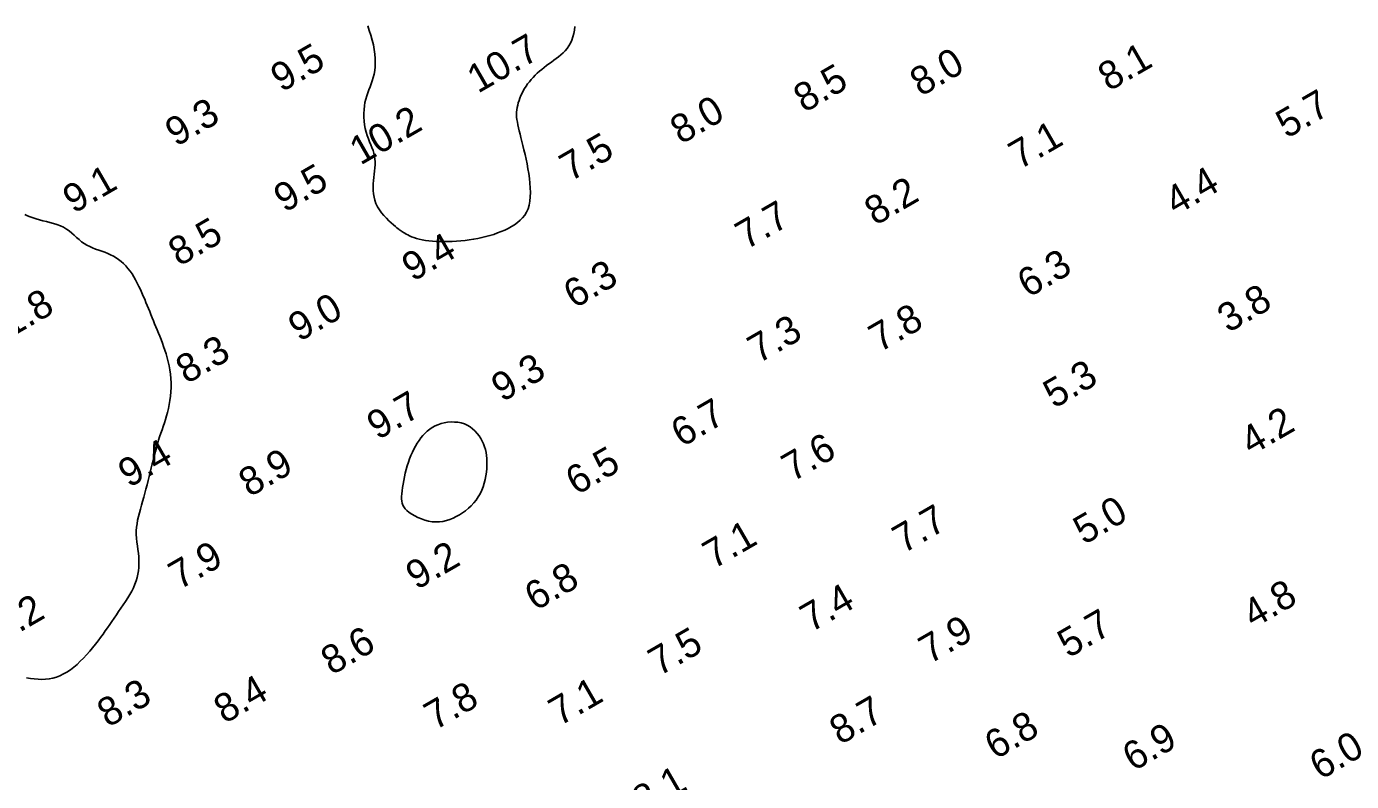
# Model space of a CAD drawing. Extents: x 3024098 to 3056816, y 418252 to 509144.
# Drawn here: x 3033611.9 to 3033845.6, y 418564.6 to 418697.7 of the extents above; entities that cross this region are included whole.
import ezdxf

# ---------------------------------------------------------------- set-up
doc = ezdxf.new("R2010")
doc.units = 0
doc.layers.add('V-CHAN-CONT-EL10', color=7, linetype='Continuous')
doc.layers.add('V-TOPO-SOUN-0911', color=7, linetype='Continuous')

msp = doc.modelspace()

# ---------------------------------------------------------------- linework, layer by layer
at = {"layer": 'V-CHAN-CONT-EL10'}
for points in [[(3033708.63, 418697.74), (3033708.55, 418697.12), (3033708.44, 418696.51), (3033708.28, 418695.92), (3033708.08, 418695.35), (3033707.84, 418694.83), (3033707.56, 418694.34), (3033707.25, 418693.89), (3033706.91, 418693.48), (3033706.55, 418693.1), (3033706.16, 418692.75), (3033705.75, 418692.42), (3033705.33, 418692.1), (3033704.9, 418691.79), (3033704.47, 418691.48), (3033704.04, 418691.17), (3033703.61, 418690.85), (3033703.19, 418690.53), (3033702.77, 418690.19), (3033702.37, 418689.85), (3033701.98, 418689.51), (3033701.6, 418689.15), (3033701.24, 418688.78), (3033700.91, 418688.4), (3033700.59, 418688.01), (3033700.29, 418687.61), (3033700.01, 418687.21), (3033699.76, 418686.8), (3033699.52, 418686.38), (3033699.3, 418685.97), (3033699.11, 418685.55), (3033698.93, 418685.13), (3033698.77, 418684.71), (3033698.64, 418684.3), (3033698.53, 418683.88), (3033698.44, 418683.46), (3033698.38, 418683.04), (3033698.35, 418682.62), (3033698.34, 418682.19), (3033698.35, 418681.77), (3033698.4, 418681.33), (3033698.47, 418680.88), (3033698.56, 418680.4), (3033698.67, 418679.9), (3033698.8, 418679.36), (3033698.95, 418678.79), (3033699.11, 418678.16), (3033699.28, 418677.48), (3033699.46, 418676.75), (3033699.64, 418675.99), (3033699.83, 418675.19), (3033700.01, 418674.36), (3033700.18, 418673.52), (3033700.34, 418672.66), (3033700.48, 418671.8), (3033700.6, 418670.95), (3033700.69, 418670.1), (3033700.75, 418669.27), (3033700.77, 418668.47), (3033700.75, 418667.69), (3033700.68, 418666.95), (3033700.55, 418666.26), (3033700.36, 418665.62), (3033700.1, 418665.03), (3033699.78, 418664.5), (3033699.4, 418664.01), (3033698.98, 418663.57), (3033698.51, 418663.17), (3033697.99, 418662.8), (3033697.44, 418662.47), (3033696.87, 418662.15), (3033696.26, 418661.86), (3033695.64, 418661.59), (3033694.99, 418661.34), (3033694.33, 418661.1), (3033693.64, 418660.89), (3033692.94, 418660.7), (3033692.22, 418660.52), (3033691.49, 418660.37), (3033690.75, 418660.23), (3033689.99, 418660.12), (3033689.24, 418660.02), (3033688.48, 418659.94), (3033687.73, 418659.88), (3033686.98, 418659.84), (3033686.24, 418659.81), (3033685.52, 418659.81), (3033684.82, 418659.82), (3033684.14, 418659.85), (3033683.48, 418659.9), (3033682.85, 418659.96), (3033682.25, 418660.04), (3033681.69, 418660.14), (3033681.16, 418660.25), (3033680.68, 418660.38), (3033680.23, 418660.52), (3033679.83, 418660.67), (3033679.47, 418660.83), (3033679.15, 418660.99), (3033678.87, 418661.14), (3033678.62, 418661.28), (3033678.41, 418661.41), (3033678.24, 418661.52), (3033678.1, 418661.61), (3033677.98, 418661.69), (3033677.86, 418661.77), (3033677.74, 418661.85), (3033677.61, 418661.95), (3033677.44, 418662.09), (3033677.23, 418662.26), (3033676.96, 418662.49), (3033676.62, 418662.77), (3033676.23, 418663.11), (3033675.81, 418663.5), (3033675.37, 418663.93), (3033674.93, 418664.4), (3033674.51, 418664.9), (3033674.13, 418665.43), (3033673.8, 418665.97), (3033673.53, 418666.53), (3033673.34, 418667.1), (3033673.2, 418667.67), (3033673.11, 418668.25), (3033673.06, 418668.84), (3033673.05, 418669.42), (3033673.07, 418670), (3033673.11, 418670.58), (3033673.17, 418671.14), (3033673.23, 418671.71), (3033673.29, 418672.26), (3033673.35, 418672.8), (3033673.38, 418673.34), (3033673.39, 418673.87), (3033673.36, 418674.39), (3033673.29, 418674.9), (3033673.17, 418675.4), (3033673.02, 418675.89), (3033672.83, 418676.39), (3033672.62, 418676.9), (3033672.4, 418677.42), (3033672.19, 418677.96), (3033671.98, 418678.52), (3033671.81, 418679.11), (3033671.66, 418679.74), (3033671.54, 418680.4), (3033671.46, 418681.07), (3033671.42, 418681.75), (3033671.41, 418682.43), (3033671.44, 418683.1), (3033671.5, 418683.75), (3033671.6, 418684.37), (3033671.74, 418684.95), (3033671.91, 418685.51), (3033672.1, 418686.04), (3033672.3, 418686.56), (3033672.5, 418687.08), (3033672.71, 418687.61), (3033672.89, 418688.16), (3033673.06, 418688.73), (3033673.2, 418689.34), (3033673.31, 418689.98), (3033673.38, 418690.66), (3033673.41, 418691.36), (3033673.4, 418692.1), (3033673.35, 418692.87), (3033673.24, 418693.67), (3033673.08, 418694.5), (3033672.87, 418695.34), (3033672.62, 418696.2), (3033672.36, 418697.05), (3033672.1, 418697.89)], [(3033611.6, 418664.61), (3033612.07, 418664.39), (3033612.56, 418664.18), (3033613.07, 418663.99), (3033613.6, 418663.81), (3033614.18, 418663.65), (3033614.78, 418663.5), (3033615.4, 418663.35), (3033616.03, 418663.2), (3033616.66, 418663.03), (3033617.27, 418662.84), (3033617.87, 418662.62), (3033618.42, 418662.35), (3033618.94, 418662.04), (3033619.42, 418661.69), (3033619.87, 418661.32), (3033620.31, 418660.93), (3033620.74, 418660.54), (3033621.17, 418660.16), (3033621.6, 418659.79), (3033622.06, 418659.47), (3033622.54, 418659.18), (3033623.04, 418658.93), (3033623.56, 418658.71), (3033624.09, 418658.51), (3033624.63, 418658.32), (3033625.16, 418658.13), (3033625.69, 418657.93), (3033626.22, 418657.73), (3033626.72, 418657.49), (3033627.22, 418657.24), (3033627.69, 418656.96), (3033628.15, 418656.65), (3033628.59, 418656.31), (3033629.01, 418655.94), (3033629.42, 418655.54), (3033629.8, 418655.1), (3033630.16, 418654.63), (3033630.51, 418654.13), (3033630.84, 418653.6), (3033631.15, 418653.06), (3033631.44, 418652.5), (3033631.73, 418651.93), (3033632, 418651.36), (3033632.25, 418650.79), (3033632.5, 418650.22), (3033632.74, 418649.66), (3033632.97, 418649.11), (3033633.19, 418648.56), (3033633.41, 418648.02), (3033633.63, 418647.48), (3033633.84, 418646.94), (3033634.06, 418646.4), (3033634.28, 418645.87), (3033634.5, 418645.33), (3033634.73, 418644.79), (3033634.95, 418644.24), (3033635.18, 418643.68), (3033635.41, 418643.12), (3033635.64, 418642.53), (3033635.87, 418641.93), (3033636.09, 418641.31), (3033636.32, 418640.67), (3033636.53, 418640.01), (3033636.73, 418639.34), (3033636.91, 418638.64), (3033637.07, 418637.93), (3033637.2, 418637.19), (3033637.3, 418636.45), (3033637.37, 418635.68), (3033637.4, 418634.9), (3033637.39, 418634.12), (3033637.36, 418633.34), (3033637.29, 418632.57), (3033637.2, 418631.82), (3033637.09, 418631.09), (3033636.95, 418630.38), (3033636.79, 418629.71), (3033636.61, 418629.07), (3033636.42, 418628.45), (3033636.22, 418627.84), (3033636.01, 418627.24), (3033635.8, 418626.64), (3033635.59, 418626.04), (3033635.38, 418625.42), (3033635.19, 418624.78), (3033635, 418624.13), (3033634.81, 418623.46), (3033634.63, 418622.78), (3033634.45, 418622.08), (3033634.27, 418621.37), (3033634.09, 418620.65), (3033633.91, 418619.91), (3033633.73, 418619.17), (3033633.54, 418618.42), (3033633.35, 418617.67), (3033633.16, 418616.92), (3033632.96, 418616.18), (3033632.77, 418615.45), (3033632.57, 418614.73), (3033632.37, 418614.02), (3033632.17, 418613.34), (3033631.98, 418612.67), (3033631.8, 418612.01), (3033631.64, 418611.36), (3033631.5, 418610.72), (3033631.39, 418610.08), (3033631.31, 418609.45), (3033631.27, 418608.8), (3033631.27, 418608.15), (3033631.31, 418607.5), (3033631.38, 418606.84), (3033631.46, 418606.18), (3033631.55, 418605.53), (3033631.63, 418604.88), (3033631.69, 418604.23), (3033631.73, 418603.6), (3033631.74, 418602.98), (3033631.71, 418602.37), (3033631.65, 418601.77), (3033631.55, 418601.17), (3033631.41, 418600.58), (3033631.23, 418599.99), (3033631.01, 418599.39), (3033630.75, 418598.8), (3033630.45, 418598.2), (3033630.11, 418597.59), (3033629.75, 418596.99), (3033629.37, 418596.38), (3033628.97, 418595.78), (3033628.56, 418595.18), (3033628.15, 418594.59), (3033627.75, 418594), (3033627.35, 418593.42), (3033626.97, 418592.86), (3033626.58, 418592.29), (3033626.2, 418591.73), (3033625.8, 418591.16), (3033625.4, 418590.59), (3033624.97, 418590.01), (3033624.53, 418589.41), (3033624.06, 418588.81), (3033623.56, 418588.19), (3033623.04, 418587.58), (3033622.51, 418586.97), (3033621.96, 418586.38), (3033621.39, 418585.82), (3033620.81, 418585.28), (3033620.23, 418584.79), (3033619.63, 418584.34), (3033619.03, 418583.93), (3033618.42, 418583.58), (3033617.8, 418583.28), (3033617.18, 418583.03), (3033616.55, 418582.84), (3033615.91, 418582.71), (3033615.26, 418582.64), (3033614.6, 418582.63), (3033613.93, 418582.66), (3033613.26, 418582.73), (3033612.58, 418582.8), (3033611.89, 418582.88)]]:
    msp.add_lwpolyline(points, dxfattribs=at)
msp.add_lwpolyline([(3033679.25, 418620.9), (3033679.46, 418621.51), (3033679.7, 418622.11), (3033679.95, 418622.68), (3033680.22, 418623.24), (3033680.51, 418623.77), (3033680.81, 418624.28), (3033681.13, 418624.76), (3033681.46, 418625.22), (3033681.82, 418625.65), (3033682.19, 418626.04), (3033682.59, 418626.41), (3033683.01, 418626.75), (3033683.46, 418627.05), (3033683.95, 418627.31), (3033684.46, 418627.54), (3033685.01, 418627.73), (3033685.59, 418627.87), (3033686.18, 418627.97), (3033686.79, 418628.02), (3033687.4, 418628.01), (3033687.99, 418627.96), (3033688.57, 418627.84), (3033689.13, 418627.67), (3033689.65, 418627.44), (3033690.13, 418627.15), (3033690.58, 418626.81), (3033691, 418626.43), (3033691.37, 418626.01), (3033691.71, 418625.57), (3033692.01, 418625.11), (3033692.27, 418624.64), (3033692.5, 418624.15), (3033692.68, 418623.66), (3033692.83, 418623.16), (3033692.95, 418622.65), (3033693.03, 418622.12), (3033693.08, 418621.57), (3033693.11, 418621.01), (3033693.1, 418620.42), (3033693.07, 418619.8), (3033693.01, 418619.17), (3033692.92, 418618.53), (3033692.79, 418617.88), (3033692.63, 418617.23), (3033692.43, 418616.59), (3033692.19, 418615.97), (3033691.9, 418615.36), (3033691.56, 418614.79), (3033691.19, 418614.24), (3033690.77, 418613.73), (3033690.32, 418613.25), (3033689.84, 418612.79), (3033689.33, 418612.37), (3033688.81, 418611.99), (3033688.26, 418611.64), (3033687.7, 418611.32), (3033687.13, 418611.04), (3033686.54, 418610.81), (3033685.95, 418610.62), (3033685.34, 418610.49), (3033684.73, 418610.41), (3033684.1, 418610.38), (3033683.46, 418610.42), (3033682.81, 418610.53), (3033682.17, 418610.7), (3033681.54, 418610.91), (3033680.94, 418611.16), (3033680.37, 418611.44), (3033679.85, 418611.75), (3033679.38, 418612.07), (3033678.99, 418612.39), (3033678.68, 418612.71), (3033678.44, 418613.03), (3033678.26, 418613.36), (3033678.15, 418613.7), (3033678.08, 418614.07), (3033678.06, 418614.47), (3033678.06, 418614.9), (3033678.1, 418615.37), (3033678.16, 418615.9), (3033678.23, 418616.46), (3033678.32, 418617.06), (3033678.43, 418617.68), (3033678.56, 418618.33), (3033678.7, 418618.98), (3033678.87, 418619.63), (3033679.05, 418620.27)], close=True, dxfattribs=at)

# ---------------------------------------------------------------- texts
at = {"layer": 'V-TOPO-SOUN-0911'}
for s, p in [('9.5', (3033656.87, 418686.07)), ('10.7 ', (3033691.52, 418685.87)), ('8.1', (3033802.79, 418686.22)), ('8.0', (3033769.62, 418685.31)), ('8.5', (3033749.09, 418682.46)), ('9.3', (3033638.27, 418676.46)), ('8.0', (3033727.33, 418676.88)), ('5.7', (3033834.17, 418677.9)), ('10.2 ', (3033670.79, 418673.2)), ('7.1', (3033787.04, 418672.44)), ('7.5', (3033707.82, 418670.32)), ('9.5', (3033657.42, 418664.84)), ('9.1', (3033620.21, 418664.66)), ('8.2', (3033761.6, 418662.55)), ('4.4', (3033814.59, 418664.35)), ('7.7', (3033738.83, 418658.31)), ('8.5', (3033638.82, 418655.36)), ('9.4', (3033680.01, 418652.67)), ('6.3', (3033788.57, 418649.82)), ('6.3', (3033708.52, 418647.91)), ('11.8 ', (3033605.83, 418640.95)), ('9.0', (3033659.98, 418642.07)), ('3.8', (3033823.84, 418643.65)), ('7.8', (3033762.36, 418640.2)), ('7.3', (3033741, 418638.24)), ('8.3', (3033640.14, 418634.63)), ('9.3', (3033695.79, 418631.44)), ('5.3', (3033793.13, 418630.3)), ('9.7', (3033673.84, 418624.75)), ('6.7', (3033727.48, 418623.47)), ('4.2', (3033827.91, 418622.03)), ('9.4', (3033629.97, 418616.32)), ('7.6', (3033747, 418617.38)), ('8.9', (3033651.23, 418614.68)), ('6.5', (3033708.9, 418615.01)), ('5.0', (3033798.43, 418606.28)), ('7.7', (3033766.55, 418604.74)), ('7.1', (3033733.07, 418602)), ('7.9', (3033638.86, 418598.34)), ('9.2', (3033680.7, 418598.31)), ('6.8', (3033701.66, 418594.6)), ('7.4', (3033750.25, 418590.83)), ('4.8', (3033828.3, 418591.55)), ('10.2 ', (3033604.19, 418587.11)), ('5.7', (3033795.66, 418586.3)), ('8.6', (3033665.73, 418583.29)), ('7.5', (3033723.47, 418583.12)), ('7.9', (3033771.18, 418585.25)), ('8.3', (3033626.27, 418574.06)), ('8.4', (3033646.84, 418574.72)), ('7.1', (3033705.91, 418574.31)), ('7.8', (3033683.94, 418573.57)), ('8.7', (3033755.43, 418571.01)), ('6.8', (3033782.79, 418568.39)), ('6.9', (3033807.11, 418566.32)), ('6.0', (3033840.1, 418564.81)), ('8.1', (3033720.7, 418558.72))]:
    msp.add_text(s, height=5, rotation=30, dxfattribs=at).set_placement(p)

doc.saveas('drawing.dxf')
